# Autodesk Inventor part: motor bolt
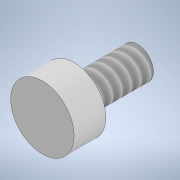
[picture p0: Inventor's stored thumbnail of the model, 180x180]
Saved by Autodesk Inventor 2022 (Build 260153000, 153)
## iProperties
Created: 2021-07
Part Number: motor bolt
Material: Generic
Document SubType Name: Modeling
Designer: Hp
Density: 1 g/cm^3
Appearance: Default
Author: Hp
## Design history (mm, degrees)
sketch "Sketch1"
  geometry: C1 r 2.5 at (0, 0); 1 further point
  constraints: 1 centre point, 1 coincident
  dimensions: "d0" = 5 diameter of C1
extrude "Extrusion1" new body sketch "Sketch1" distance "d1" = 10; taper "d2" = 0 deg
sketch "Sketch2"
  geometry: C1 r 5 at (0, 0); 1 further point
  constraints: 1 centre point, 1 coincident
  dimensions: "d3" = 10 diameter of C1
extrude "Extrusion2" join sketch "Sketch2" distance "d4" = 5; taper "d5" = 0 deg
thread "Thread2" dims "d8" = 10, "d9" = 0
body "Solid1"
